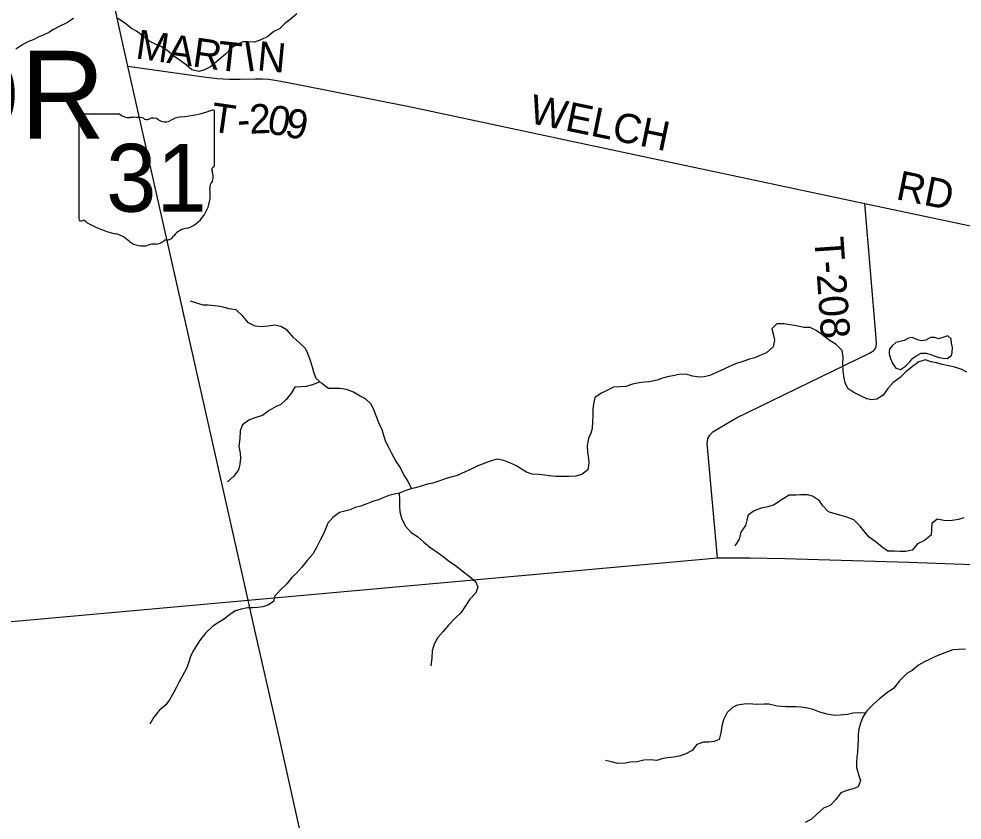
# Model space of a CAD drawing. Extents: x 0 to 34, y 0 to 22.
# Drawn here: x 6.665 to 7.582, y 15.21 to 15.989 of the extents above; entities that cross this region are included whole.
import ezdxf

# ---------------------------------------------------------------- set-up
doc = ezdxf.new("R2010")
doc.units = 0
for name, color, linetype in [('GM_X_County_Road', 7, 'Continuous'), ('GM_X_Minor_Lake', 7, 'Continuous'), ('GM_X_Minor_River', 7, 'Continuous'), ('GM_X_State_Location', 7, 'Continuous'), ('GM_X_State_Route', 7, 'Continuous'), ('GM_X_State_Shield', 7, 'Continuous'), ('GM_X_Township_Road', 7, 'Continuous'), ('GM_X_Township_Road_Text', 7, 'Continuous'), ('GM_X_Township_Text', 7, 'Continuous')]:
    doc.layers.add(name, color=color, linetype=linetype)

msp = doc.modelspace()

# ---------------------------------------------------------------- linework, layer by layer
at = {"layer": 'GM_X_County_Road'}
for points in [[(6.88802, 15.42373), (7.34435, 15.46475), (7.37608, 15.465), (7.40991, 15.46424), (7.53074, 15.46071), (7.78545, 15.45126)], [(5.74602, 15.26769), (5.75387, 15.27182), (5.7631, 15.27526), (5.77623, 15.27825), (5.89318, 15.29939), (6.26193, 15.36747), (6.88802, 15.42373)]]:
    msp.add_lwpolyline(points, dxfattribs=at)
at = {"layer": 'GM_X_Minor_Lake'}
for points in [[(7.57035, 15.66051), (7.57199, 15.66169), (7.57275, 15.66453), (7.57315, 15.66928), (7.57222, 15.67364), (7.57186, 15.67782), (7.56864, 15.68068), (7.56447, 15.67937), (7.55934, 15.67768), (7.55556, 15.67902), (7.55158, 15.67903), (7.54702, 15.67659), (7.54246, 15.67584), (7.53849, 15.677), (7.53394, 15.6791), (7.53015, 15.67835), (7.52597, 15.67628), (7.52217, 15.67516), (7.51781, 15.67423), (7.51438, 15.67082), (7.51172, 15.6678)], [(7.51172, 15.6678), (7.51133, 15.6659), (7.51151, 15.66305), (7.51282, 15.65868), (7.51489, 15.65355), (7.51809, 15.64918), (7.52245, 15.64802), (7.52739, 15.65123), (7.53139, 15.6552), (7.53463, 15.65898), (7.53843, 15.66162), (7.54261, 15.66389), (7.54735, 15.66387), (7.55151, 15.66253), (7.55625, 15.6608), (7.56022, 15.65965), (7.56401, 15.65906), (7.5678, 15.65867), (7.57035, 15.66051)]]:
    msp.add_lwpolyline(points, dxfattribs=at)
at = {"layer": 'GM_X_Minor_River'}
for points in [[(6.93531, 15.99353), (6.92884, 15.98824), (6.92352, 15.9839), (6.91839, 15.97918), (6.91308, 15.97654), (6.90718, 15.97163), (6.90035, 15.96843), (6.89409, 15.96618), (6.88765, 15.96639), (6.88273, 15.96641), (6.87742, 15.96378), (6.87191, 15.96076), (6.86601, 15.95453), (6.85974, 15.94943), (6.85138, 15.94206), (6.8455, 15.93924), (6.84019, 15.93774), (6.83318, 15.93928), (6.8279, 15.94367), (6.82185, 15.94843), (6.81562, 15.95244), (6.80882, 15.95834), (6.80296, 15.96197), (6.79805, 15.96426), (6.79181, 15.96694), (6.78482, 15.97247), (6.77953, 15.97666), (6.77462, 15.97953), (6.76763, 15.98486), (6.76121, 15.98906)], [(6.71802, 15.98922), (6.71156, 15.98507), (6.70435, 15.98149), (6.69884, 15.97829), (6.6941, 15.97565), (6.68878, 15.97283), (6.68385, 15.97114), (6.67891, 15.9685), (6.6736, 15.96643), (6.66791, 15.96323), (6.66202, 15.95946)], [(7.04705, 15.53214), (7.04348, 15.53974), (7.03933, 15.54545), (7.03576, 15.55286), (7.03161, 15.55914), (7.02766, 15.56637), (7.02446, 15.57283), (7.02202, 15.57758), (7.02033, 15.5829), (7.01846, 15.58936), (7.01526, 15.5962), (7.01264, 15.60285), (7.00982, 15.60969), (7.00719, 15.61463), (7.00209, 15.61958), (6.99698, 15.62207), (6.99037, 15.62589), (6.98375, 15.62857), (6.97712, 15.62935), (6.96613, 15.62939), (6.95971, 15.63435), (6.95405, 15.6393), (6.9518, 15.64538), (6.95068, 15.65013), (6.94824, 15.65735), (6.94599, 15.66362), (6.94392, 15.66837), (6.93788, 15.67389), (6.93222, 15.67903), (6.926, 15.68626), (6.91976, 15.6897), (6.9137, 15.69105), (6.90745, 15.69013), (6.90119, 15.68939), (6.89475, 15.69018), (6.88833, 15.69343), (6.88286, 15.6997), (6.87644, 15.7058), (6.86962, 15.70677), (6.86243, 15.7087), (6.85562, 15.70986), (6.84918, 15.71045), (6.84425, 15.71047), (6.83915, 15.7122), (6.83196, 15.71431)], [(7.58709, 15.6455), (7.58217, 15.6478), (7.57517, 15.65029), (7.56929, 15.65145), (7.56285, 15.6528), (7.55736, 15.65434), (7.55206, 15.6555), (7.54694, 15.65723), (7.5403, 15.65555), (7.53403, 15.65082), (7.52775, 15.64553), (7.52204, 15.64024), (7.51539, 15.63533), (7.51006, 15.62947), (7.50548, 15.62303), (7.4994, 15.61926), (7.49466, 15.61852), (7.48973, 15.61949), (7.48368, 15.62235), (7.47705, 15.6256), (7.47119, 15.62942), (7.46875, 15.63494), (7.46725, 15.64139), (7.4667, 15.64671), (7.46654, 15.65316), (7.46675, 15.65999), (7.46564, 15.66645), (7.45979, 15.67235), (7.45297, 15.67636), (7.44598, 15.68189), (7.4405, 15.6859), (7.43463, 15.68877), (7.42837, 15.68879), (7.42136, 15.69033), (7.41511, 15.6915), (7.40886, 15.69228), (7.40222, 15.6923), (7.39747, 15.68758), (7.39858, 15.68245), (7.39989, 15.67637), (7.39854, 15.67011), (7.39207, 15.66407), (7.38561, 15.66143), (7.38068, 15.65936), (7.37574, 15.65805), (7.3691, 15.6558), (7.36188, 15.65336), (7.35695, 15.6511), (7.35011, 15.6479), (7.34346, 15.64489), (7.337, 15.64207), (7.3315, 15.64095), (7.32676, 15.64059), (7.32032, 15.64137), (7.31407, 15.64329), (7.30724, 15.64313), (7.30117, 15.64182), (7.29586, 15.64089), (7.29111, 15.63958), (7.2858, 15.63751), (7.2784, 15.63583), (7.27347, 15.63566), (7.26835, 15.63511), (7.2617, 15.63362), (7.25544, 15.63155), (7.24975, 15.631), (7.24349, 15.63084), (7.23172, 15.62479)], [(6.9578, 15.63602), (6.95061, 15.63305), (6.94455, 15.63137), (6.93943, 15.6312), (6.93337, 15.63065), (6.93032, 15.62535), (6.92499, 15.61873), (6.91986, 15.61401), (6.91512, 15.61194), (6.90847, 15.60798), (6.90182, 15.60307), (6.89538, 15.6012), (6.88874, 15.59857), (6.88247, 15.59403), (6.88037, 15.58816), (6.87977, 15.58095), (6.87899, 15.57356), (6.8801, 15.56672), (6.88046, 15.56179), (6.88006, 15.55591), (6.87872, 15.55041), (6.87415, 15.54436), (6.86788, 15.53888)], [(7.23172, 15.62479), (7.22505, 15.62084), (7.22389, 15.61439), (7.2233, 15.60927), (7.22309, 15.60244), (7.22307, 15.59732), (7.22248, 15.59068), (7.22132, 15.58594), (7.21903, 15.58083), (7.21787, 15.57401), (7.21804, 15.56736), (7.21896, 15.56186), (7.21932, 15.55711), (7.21835, 15.55048), (7.21265, 15.54594), (7.20678, 15.54426), (7.19996, 15.54391), (7.18726, 15.54395), (7.18121, 15.54473), (7.17628, 15.54532), (7.1706, 15.54572), (7.16416, 15.54632), (7.15886, 15.54804), (7.15395, 15.5511), (7.14885, 15.55415), (7.14317, 15.55683), (7.13674, 15.55932), (7.13012, 15.56067), (7.12348, 15.55899), (7.11836, 15.55692), (7.11153, 15.55429), (7.10489, 15.5509), (7.09901, 15.54846), (7.09142, 15.54488), (7.08649, 15.54357), (7.08061, 15.54188), (7.07359, 15.53944), (7.06772, 15.53757), (7.0626, 15.53645), (7.05634, 15.53438), (7.05084, 15.53289), (7.0461, 15.53196), (7.04136, 15.53027), (7.0351, 15.52782), (7.02998, 15.5267), (7.02486, 15.52539), (7.02012, 15.52351), (7.01481, 15.52126), (7.01007, 15.51995), (7.00343, 15.51732), (6.99755, 15.51506), (6.99224, 15.51375), (6.98731, 15.51168), (6.98219, 15.51018), (6.97688, 15.50907), (6.97023, 15.50397), (6.96548, 15.49848), (6.96318, 15.4928), (6.96051, 15.48693), (6.95803, 15.482), (6.95441, 15.475), (6.95079, 15.46856), (6.94527, 15.46232), (6.94033, 15.45569), (6.93519, 15.45002), (6.93044, 15.44567), (6.92549, 15.43962), (6.91903, 15.43357), (6.91352, 15.42714), (6.91255, 15.4224), (6.90705, 15.41881), (6.90231, 15.41731), (6.89738, 15.41657), (6.89265, 15.4164), (6.88734, 15.41642), (6.88127, 15.41512), (6.87578, 15.41324), (6.87103, 15.41041), (6.864, 15.40493), (6.85926, 15.40191), (6.85356, 15.39852), (6.84653, 15.39152), (6.84082, 15.38433), (6.83759, 15.37903), (6.83416, 15.37373), (6.83187, 15.36881), (6.82995, 15.36293), (6.82823, 15.358), (6.82423, 15.35024), (6.8208, 15.34418), (6.81832, 15.33925), (6.81565, 15.33414), (6.81165, 15.32694), (6.80803, 15.32183), (6.80139, 15.31654), (6.79644, 15.30992), (6.79244, 15.3031)], [(7.0349, 15.52778), (7.03526, 15.52118), (7.03524, 15.51473), (7.0356, 15.50961), (7.03747, 15.50239), (7.04105, 15.49573), (7.04652, 15.48945), (7.05257, 15.48545), (7.05899, 15.48011), (7.06598, 15.4742), (7.07165, 15.47076), (7.07769, 15.46619), (7.08374, 15.46123), (7.08941, 15.45761), (7.09621, 15.45208), (7.10282, 15.44712), (7.10905, 15.44197), (7.11131, 15.43684), (7.10958, 15.43078), (7.10369, 15.42473), (7.09931, 15.4181), (7.09512, 15.41185), (7.08904, 15.406), (7.08296, 15.39957), (7.07744, 15.39294), (7.0725, 15.38746), (7.06888, 15.38083), (7.06715, 15.37458), (7.06656, 15.36737), (7.06559, 15.35978)], [(7.58411, 15.50375), (7.5788, 15.50206), (7.57064, 15.50095), (7.56476, 15.50116), (7.55813, 15.50251), (7.553, 15.49817), (7.55279, 15.49285), (7.5522, 15.48697), (7.54573, 15.48168), (7.53909, 15.47848), (7.53395, 15.47243), (7.52731, 15.47093), (7.52181, 15.47114), (7.5165, 15.47135), (7.51005, 15.47137), (7.50476, 15.47519), (7.49928, 15.47976), (7.4919, 15.48511), (7.4868, 15.49101), (7.48322, 15.49577), (7.47698, 15.50168), (7.47017, 15.50455), (7.46354, 15.50628), (7.45748, 15.50782), (7.45255, 15.50974), (7.44708, 15.51526), (7.44368, 15.5204), (7.43687, 15.52479), (7.43195, 15.52595), (7.4255, 15.52616), (7.42057, 15.5258), (7.41412, 15.52582), (7.40671, 15.5211), (7.39968, 15.51639), (7.39361, 15.51432), (7.38697, 15.51302), (7.38032, 15.51057), (7.37424, 15.50623), (7.37308, 15.50149), (7.37174, 15.49618), (7.36716, 15.48975), (7.36543, 15.48311), (7.36124, 15.47667)], [(7.58575, 15.376), (7.57873, 15.37584), (7.57342, 15.37528), (7.56564, 15.37266), (7.56051, 15.37059), (7.55577, 15.36852), (7.55064, 15.36607), (7.54589, 15.36381), (7.54, 15.3606), (7.53373, 15.3555), (7.5286, 15.35229), (7.52156, 15.34529), (7.51604, 15.3381), (7.50977, 15.33395), (7.50197, 15.3279), (7.49627, 15.32261), (7.48961, 15.31599), (7.48618, 15.31069), (7.4835, 15.30405), (7.48197, 15.29836), (7.48138, 15.29343), (7.48136, 15.28849), (7.48096, 15.28166), (7.48075, 15.27616), (7.47998, 15.27103), (7.47977, 15.26591), (7.47975, 15.26097), (7.48181, 15.25337), (7.48369, 15.24843), (7.48121, 15.24236), (7.47646, 15.24029), (7.47039, 15.23861), (7.46431, 15.23654), (7.45955, 15.2301), (7.45423, 15.22424), (7.44758, 15.22142), (7.4415, 15.21593), (7.43598, 15.21083), (7.42971, 15.20762)], [(7.48816, 15.31375), (7.4824, 15.31412), (7.47614, 15.31376), (7.47102, 15.31264), (7.46381, 15.31191), (7.45888, 15.31155), (7.45111, 15.3129), (7.4441, 15.31483), (7.43766, 15.31732), (7.43217, 15.31886), (7.42573, 15.31983), (7.42099, 15.32004), (7.41094, 15.32008), (7.4026, 15.32068), (7.39446, 15.3226), (7.38953, 15.32262), (7.38213, 15.32246), (7.3755, 15.32286), (7.37057, 15.32269), (7.36374, 15.32158), (7.35899, 15.31951), (7.35405, 15.31459), (7.35023, 15.30739), (7.34869, 15.30113), (7.34772, 15.29468), (7.34599, 15.28842), (7.34125, 15.28635), (7.33613, 15.2858), (7.33101, 15.28563), (7.32455, 15.28357), (7.31979, 15.27751), (7.31315, 15.27393), (7.30708, 15.27224), (7.30214, 15.27112), (7.2955, 15.27039), (7.29038, 15.26945), (7.28564, 15.26795), (7.279, 15.26836), (7.27274, 15.26819), (7.26648, 15.26669), (7.26004, 15.26634), (7.25491, 15.26522), (7.24771, 15.26506), (7.24146, 15.2666), (7.23558, 15.26795)]]:
    msp.add_lwpolyline(points, dxfattribs=at)
at = {"layer": 'GM_X_State_Route'}
for points in [[(6.86596, 15.52165), (6.77115, 15.94274), (6.76483, 15.97036), (6.75304, 16.02412), (6.74298, 16.06886), (6.73535, 16.10239), (6.72194, 16.16193), (6.70413, 16.24021), (6.69194, 16.29465), (6.64963, 16.4835), (6.54347, 16.95482), (6.52418, 17.04067), (6.50038, 17.14713), (6.49302, 17.17924)], [(6.89464, 15.3945), (6.88802, 15.42373), (6.86596, 15.52165)], [(6.9891, 14.97346), (6.95075, 15.14507), (6.93627, 15.20932), (6.91814, 15.29075), (6.89464, 15.3945)]]:
    msp.add_lwpolyline(points, dxfattribs=at)
at = {"layer": 'GM_X_State_Shield'}
for p, q in [((6.72346, 15.89434), (6.72346, 15.79428)), ((6.76336, 15.89606), (6.72476, 15.89606)), ((6.85529, 15.8462), (6.85529, 15.89854)), ((6.85528, 15.84621), (6.85529, 15.8462))]:
    msp.add_line(p, q, dxfattribs=at)
for centre, radius, start, end in [((6.80833, 16.03247), 0.13981, 275.84447, 288.90645), ((6.85383, 15.89875), 0.00147, 351.86209, 97.738), ((6.72497, 15.89455), 0.00153, 98.1301, 188.1301), ((6.77256, 15.90767), 0.01481, 231.61951, 271.11188), ((6.77747, 15.83988), 0.05318, 80.48669, 94.98827), ((6.78954, 15.89507), 0.00427, 219.79206, 297.10237), ((6.79582, 15.8835), 0.00889, 54.46668, 119.14113), ((6.80729, 15.89937), 0.01069, 233.85621, 294.82819), ((6.82616, 15.8655), 0.02813, 97.34618, 120.76885), ((6.85495, 15.84235), 0.00227, 107.94398, 210.33697), ((6.85373, 15.84599), 0.00157, 289.60381, 7.73413), ((6.8405, 15.83574), 0.01363, 340.03296, 23.64957), ((6.86055, 15.82429), 0.00992, 136.8065, 186.92959), ((6.81616, 15.81763), 0.03497, 292.30889, 8.98584), ((6.72498, 15.79406), 0.00154, 171.95839, 258.30661), ((6.72522, 15.80429), 0.01176, 267.33899, 280.60386), ((6.72762, 15.7885), 0.00424, 29.74838, 93.27175), ((6.78115, 15.8784), 0.10096, 240.41292, 257.1985), ((6.75105, 15.74932), 0.03159, 47.18416, 75.83597), ((6.83091, 15.76618), 0.01915, 94.40312, 142.57675), ((6.78522, 15.78801), 0.02004, 230.70037, 286.29184), ((6.79826, 15.78051), 0.01068, 268.77702, 315.54927), ((6.80792, 15.77082), 0.00301, 65.75173, 132.64842), ((6.80664, 15.78458), 0.0113, 282.87319, 323.27711), ((6.7968, 15.75341), 0.01647, 85.69512, 111.20995)]:
    msp.add_arc(centre, radius, start, end, dxfattribs=at)
at = {"layer": 'GM_X_Township_Road'}
for points in [[(6.77115, 15.94274), (6.84494, 15.9325), (6.85796, 15.93096), (6.86954, 15.9303), (6.88024, 15.93019), (6.89523, 15.93049), (6.90211, 15.93055), (6.90796, 15.93024), (6.91623, 15.92901), (6.93517, 15.92531), (7.04635, 15.90319), (7.23612, 15.86264), (7.48786, 15.80943), (7.66254, 15.77226)], [(7.34435, 15.46475), (7.33509, 15.569), (7.33452, 15.5761), (7.33523, 15.58083), (7.3371, 15.5842), (7.34011, 15.58729), (7.34635, 15.59138), (7.36285, 15.60092), (7.4924, 15.66375), (7.4967, 15.66648), (7.49842, 15.66899), (7.49907, 15.67258), (7.49892, 15.67831), (7.48786, 15.80943)]]:
    msp.add_lwpolyline(points, dxfattribs=at)

# ---------------------------------------------------------------- texts
at = {"layer": 'GM_X_State_Location'}
for s, p in [('s', (6.78789, 15.83765)), ('r', (6.78788, 15.83765))]:
    msp.add_text(s, height=0.0000947, dxfattribs=at).set_placement(p)
msp.add_text('31', height=0.0000947, rotation=0.00001, dxfattribs=at).set_placement((6.76404, 15.83076))
at = {"layer": 'GM_X_State_Shield'}
msp.add_text('31', height=0.065918, dxfattribs=at).set_placement((6.74981, 15.80133))
at = {"layer": 'GM_X_Township_Road_Text'}
for s, height, rotation, p in [('M', 0.02841, 351.97557, (6.77769, 15.95044)), ('A', 0.02841, 351.97447, (6.80822, 15.94614)), ('R', 0.02841, 351.97765, (6.83298, 15.94265)), ('T', 0.02841, 353.68422, (6.857, 15.93927)), ('I', 0.02841, 9.10235, (6.88644, 15.93714)), ('N', 0.02841, 354.59351, (6.89607, 15.93892)), ('WELCH', 0.028409, 348.36113, (7.16012, 15.88781)), ('T', 0.02841, 351.8602, (6.85046, 15.8795)), ('2', 0.02841, 2.12379, (6.88955, 15.87712)), ('0', 0.02841, 349.41263, (6.90538, 15.87789)), ('9', 0.02841, 349.41234, (6.92258, 15.87467)), ('-', 0.02841, 4.28621, (6.8782, 15.87626)), ('RD', 0.028409, 348.49418, (7.5171, 15.81365)), ('T-208', 0.028409, 273.92586, (7.4386, 15.776))]:
    msp.add_text(s, height=height, rotation=rotation, dxfattribs=at).set_placement(p)
at = {"layer": 'GM_X_Township_Text'}
msp.add_text('TAYLOR', height=0.085227, rotation=0.00001, dxfattribs=at).set_placement((6.29278, 15.87248))

doc.saveas('drawing.dxf')
